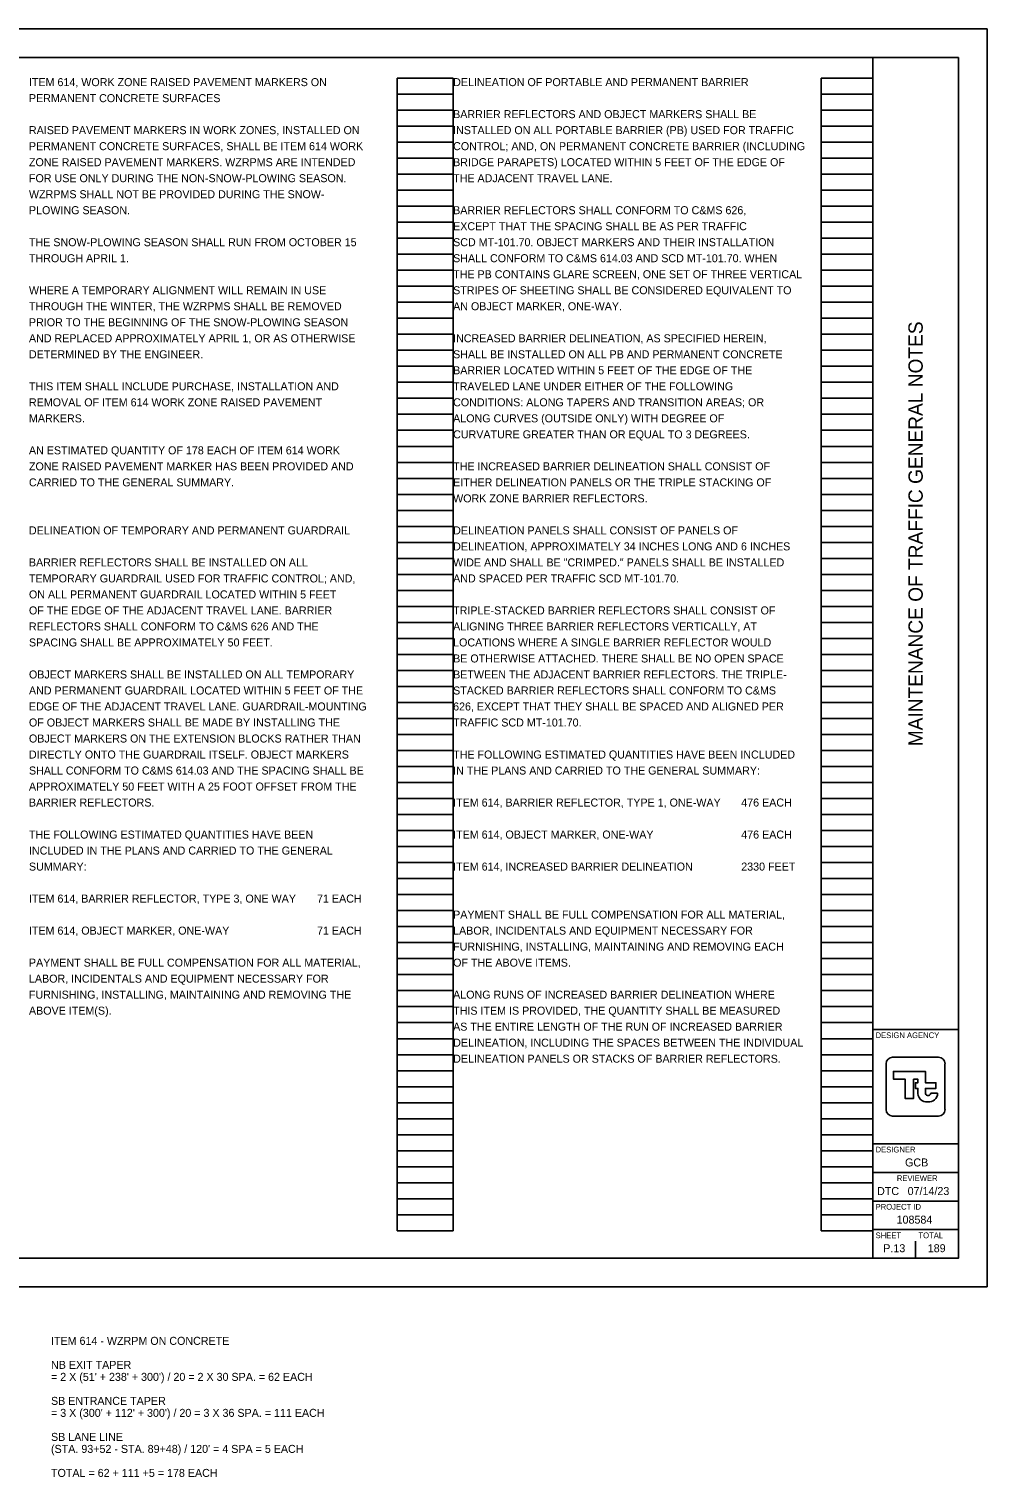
# Model space of a CAD drawing. Extents: x 0 to 34, y -4 to 22.
# Drawn here: x 17.24 to 34, y -3.33 to 22 of the extents above; entities that cross this region are included whole.
import ezdxf

# ---------------------------------------------------------------- set-up
doc = ezdxf.new("R2010")
doc.units = 0
for name, color, linetype in [('SH_Border', 7, 'Continuous'), ('SH_Cut_Line', 7, 'Continuous'), ('SH_Data', 7, 'Continuous'), ('SH_Text', 7, 'Continuous')]:
    doc.layers.add(name, color=color, linetype=linetype)

msp = doc.modelspace()

# ---------------------------------------------------------------- linework, layer by layer
at = {"layer": 'SH_Border'}
for p, q in [((32, 0.5), (32, 21.5)), ((32, 4.5), (33.5, 4.5)), ((32, 2.5), (33.5, 2.5)), ((32, 2), (33.5, 2)), ((32, 1.5), (33.5, 1.5)), ((32, 1), (33.5, 1))]:
    msp.add_line(p, q, dxfattribs=at)
msp.add_lwpolyline([(1.5, 21.5), (33.5, 21.5), (33.5, 0.5), (1.5, 0.5)], close=True, dxfattribs=at)
at = {"layer": 'SH_Cut_Line'}
msp.add_lwpolyline([(0, 0), (34, 0), (34, 22), (0, 22)], close=True, dxfattribs=at)
at = {"layer": 'SH_Data'}
for p, q in [((23.68, 0.98), (23.68, 21.14)), ((23.68, 21.14), (24.66, 21.14)), ((24.66, 0.98), (24.66, 21.14)), ((31.1, 0.98), (31.1, 21.14)), ((31.1, 21.14), (32, 21.14)), ((32, 0.98), (32, 21.14)), ((23.68, 20.86), (24.66, 20.86)), ((31.1, 20.86), (32, 20.86)), ((23.68, 20.58), (24.66, 20.58)), ((31.1, 20.58), (32, 20.58)), ((23.68, 20.3), (24.66, 20.3)), ((31.1, 20.3), (32, 20.3)), ((23.68, 20.02), (24.66, 20.02)), ((31.1, 20.02), (32, 20.02)), ((23.68, 19.74), (24.66, 19.74)), ((31.1, 19.74), (32, 19.74)), ((23.68, 19.46), (24.66, 19.46)), ((31.1, 19.46), (32, 19.46)), ((23.68, 19.18), (24.66, 19.18)), ((31.1, 19.18), (32, 19.18)), ((23.68, 18.9), (24.66, 18.9)), ((31.1, 18.9), (32, 18.9)), ((23.68, 18.62), (24.66, 18.62)), ((31.1, 18.62), (32, 18.62)), ((23.68, 18.34), (24.66, 18.34)), ((31.1, 18.34), (32, 18.34)), ((23.68, 18.06), (24.66, 18.06)), ((31.1, 18.06), (32, 18.06)), ((23.68, 17.78), (24.66, 17.78)), ((31.1, 17.78), (32, 17.78)), ((23.68, 17.5), (24.66, 17.5)), ((31.1, 17.5), (32, 17.5)), ((23.68, 17.22), (24.66, 17.22)), ((31.1, 17.22), (32, 17.22)), ((23.68, 16.94), (24.66, 16.94)), ((31.1, 16.94), (32, 16.94)), ((23.68, 16.66), (24.66, 16.66)), ((31.1, 16.66), (32, 16.66)), ((23.68, 16.38), (24.66, 16.38)), ((31.1, 16.38), (32, 16.38)), ((23.68, 16.1), (24.66, 16.1)), ((31.1, 16.1), (32, 16.1)), ((23.68, 15.82), (24.66, 15.82)), ((31.1, 15.82), (32, 15.82)), ((23.68, 15.54), (24.66, 15.54)), ((31.1, 15.54), (32, 15.54)), ((23.68, 15.26), (24.66, 15.26)), ((31.1, 15.26), (32, 15.26)), ((23.68, 14.98), (24.66, 14.98)), ((31.1, 14.98), (32, 14.98)), ((23.68, 14.7), (24.66, 14.7)), ((31.1, 14.7), (32, 14.7)), ((23.68, 14.42), (24.66, 14.42)), ((31.1, 14.42), (32, 14.42)), ((23.68, 14.14), (24.66, 14.14)), ((31.1, 14.14), (32, 14.14)), ((23.68, 13.86), (24.66, 13.86)), ((31.1, 13.86), (32, 13.86)), ((23.68, 13.58), (24.66, 13.58)), ((31.1, 13.58), (32, 13.58)), ((23.68, 13.3), (24.66, 13.3)), ((31.1, 13.3), (32, 13.3)), ((23.68, 13.02), (24.66, 13.02)), ((31.1, 13.02), (32, 13.02)), ((23.68, 12.74), (24.66, 12.74)), ((31.1, 12.74), (32, 12.74)), ((23.68, 12.46), (24.66, 12.46)), ((31.1, 12.46), (32, 12.46)), ((23.68, 12.18), (24.66, 12.18)), ((31.1, 12.18), (32, 12.18)), ((23.68, 11.9), (24.66, 11.9)), ((31.1, 11.9), (32, 11.9)), ((23.68, 11.62), (24.66, 11.62)), ((31.1, 11.62), (32, 11.62)), ((23.68, 11.34), (24.66, 11.34)), ((31.1, 11.34), (32, 11.34)), ((23.68, 11.06), (24.66, 11.06)), ((31.1, 11.06), (32, 11.06)), ((23.68, 10.78), (24.66, 10.78)), ((31.1, 10.78), (32, 10.78)), ((23.68, 10.5), (24.66, 10.5)), ((31.1, 10.5), (32, 10.5)), ((23.68, 10.22), (24.66, 10.22)), ((31.1, 10.22), (32, 10.22)), ((23.68, 9.94), (24.66, 9.94)), ((31.1, 9.94), (32, 9.94)), ((23.68, 9.66), (24.66, 9.66)), ((31.1, 9.66), (32, 9.66)), ((23.68, 9.38), (24.66, 9.38)), ((31.1, 9.38), (32, 9.38)), ((23.68, 9.1), (24.66, 9.1)), ((31.1, 9.1), (32, 9.1)), ((23.68, 8.82), (24.66, 8.82)), ((31.1, 8.82), (32, 8.82)), ((23.68, 8.54), (24.66, 8.54)), ((31.1, 8.54), (32, 8.54)), ((23.68, 8.26), (24.66, 8.26)), ((31.1, 8.26), (32, 8.26)), ((23.68, 7.98), (24.66, 7.98)), ((31.1, 7.98), (32, 7.98)), ((23.68, 7.7), (24.66, 7.7)), ((31.1, 7.7), (32, 7.7)), ((23.68, 7.42), (24.66, 7.42)), ((31.1, 7.42), (32, 7.42)), ((23.68, 7.14), (24.66, 7.14)), ((31.1, 7.14), (32, 7.14)), ((23.68, 6.86), (24.66, 6.86)), ((31.1, 6.86), (32, 6.86)), ((23.68, 6.58), (24.66, 6.58)), ((31.1, 6.58), (32, 6.58)), ((23.68, 6.3), (24.66, 6.3)), ((31.1, 6.3), (32, 6.3)), ((23.68, 6.02), (24.66, 6.02)), ((31.1, 6.02), (32, 6.02)), ((23.68, 5.74), (24.66, 5.74)), ((31.1, 5.74), (32, 5.74)), ((23.68, 5.46), (24.66, 5.46)), ((31.1, 5.46), (32, 5.46)), ((23.68, 5.18), (24.66, 5.18)), ((31.1, 5.18), (32, 5.18)), ((23.68, 4.9), (24.66, 4.9)), ((31.1, 4.9), (32, 4.9)), ((23.68, 4.62), (24.66, 4.62)), ((31.1, 4.62), (32, 4.62)), ((23.68, 4.34), (24.66, 4.34)), ((31.1, 4.34), (32, 4.34)), ((23.68, 4.06), (24.66, 4.06)), ((31.1, 4.06), (32, 4.06)), ((23.68, 3.78), (24.66, 3.78)), ((31.1, 3.78), (32, 3.78)), ((23.68, 3.5), (24.66, 3.5)), ((31.1, 3.5), (32, 3.5)), ((32.75, 3.5), (32.75, 3.5)), ((32.791, 3.415), (32.791, 3.415)), ((33.136, 3.385), (33.015, 3.385)), ((23.68, 3.22), (24.66, 3.22)), ((31.1, 3.22), (32, 3.22)), ((23.68, 2.94), (24.66, 2.94)), ((31.1, 2.94), (32, 2.94)), ((23.68, 2.66), (24.66, 2.66)), ((31.1, 2.66), (32, 2.66)), ((23.68, 2.38), (24.66, 2.38)), ((31.1, 2.38), (32, 2.38)), ((23.68, 2.1), (24.66, 2.1)), ((31.1, 2.1), (32, 2.1)), ((23.68, 1.82), (24.66, 1.82)), ((31.1, 1.82), (32, 1.82)), ((23.68, 1.54), (24.66, 1.54)), ((31.1, 1.54), (32, 1.54)), ((23.68, 1.26), (24.66, 1.26)), ((31.1, 1.26), (32, 1.26)), ((23.68, 0.98), (24.66, 0.98)), ((31.1, 0.98), (32, 0.98)), ((32.75, 0.5), (32.75, 0.8)), ((32.375, 0.675), (32.375, 0.675))]:
    msp.add_line(p, q, dxfattribs=at)
for points in [[(32.236, 3.099), (32.236, 3.901)], [(32.348, 4.014), (33.152, 4.014)], [(33.264, 3.901), (33.264, 3.099)], [(32.922, 3.399), (32.922, 3.47), (33.107, 3.47), (33.107, 3.568), (32.922, 3.568), (32.922, 3.768), (32.361, 3.768), (32.361, 3.632), (32.566, 3.632), (32.566, 3.294), (32.715, 3.294), (32.715, 3.63), (32.79, 3.63), (32.79, 3.568), (32.748, 3.568), (32.748, 3.47), (32.79, 3.47), (32.79, 3.415), (32.791, 3.415)], [(33.152, 2.986), (32.348, 2.986)]]:
    msp.add_lwpolyline(points, dxfattribs=at)
for centre, radius, start, end in [((32.348, 3.901), 0.113, 90, 180), ((33.152, 3.901), 0.113, 360, 90), ((32.949, 3.392), 0.16, 171.8856, 274.8323), ((32.968, 3.392), 0.0473, 171.8856, 350.9243), ((32.976, 3.392), 0.16, 265.1677, 357.3201), ((32.348, 3.099), 0.113, 180, 270), ((33.152, 3.099), 0.113, 270, 360)]:
    msp.add_arc(centre, radius, start, end, dxfattribs=at)

# ---------------------------------------------------------------- texts
msp.add_text('MAINTENANCE OF TRAFFIC GENERAL NOTES', height=0.25, rotation=90, dxfattribs=at).set_placement((32.875, 9.455))
for s, height, p in [('DESIGN AGENCY', 0.1, (32.05, 4.35)), ('DESIGNER', 0.1, (32.05, 2.35)), ('GCB', 0.14, (32.566, 2.105)), ('REVIEWER', 0.1, (32.422, 1.85)), ('DTC', 0.14, (32.076, 1.605)), ('07/14/23', 0.14, (32.611, 1.605)), ('PROJECT ID', 0.1, (32.05, 1.35)), ('108584', 0.14, (32.418, 1.105)), ('SHEET', 0.1, (32.05, 0.85)), ('TOTAL', 0.1, (32.8, 0.85)), ('P.13', 0.14, (32.185, 0.605)), ('189', 0.14, (32.963, 0.605))]:
    msp.add_text(s, height=height, dxfattribs=at).set_placement(p)
at = {"layer": 'SH_Text'}
for s, p in [('ITEM 614, WORK ZONE RAISED PAVEMENT MARKERS ON', (17.24, 21)), ('DELINEATION OF PORTABLE AND PERMANENT BARRIER', (24.66, 21)), ('PERMANENT CONCRETE SURFACES', (17.24, 20.72)), ('BARRIER REFLECTORS AND OBJECT MARKERS SHALL BE', (24.66, 20.44)), ('RAISED PAVEMENT MARKERS IN WORK ZONES, INSTALLED ON', (17.24, 20.16)), ('INSTALLED ON ALL PORTABLE BARRIER (PB) USED FOR TRAFFIC', (24.66, 20.16)), ('PERMANENT CONCRETE SURFACES, SHALL BE ITEM 614 WORK', (17.24, 19.88)), ('CONTROL; AND, ON PERMANENT CONCRETE BARRIER (INCLUDING', (24.66, 19.88)), ('ZONE RAISED PAVEMENT MARKERS. WZRPMS ARE INTENDED', (17.24, 19.6)), ('BRIDGE PARAPETS) LOCATED WITHIN 5 FEET OF THE EDGE OF', (24.66, 19.6)), ('FOR USE ONLY DURING THE NON-SNOW-PLOWING SEASON.', (17.24, 19.32)), ('THE ADJACENT TRAVEL LANE.', (24.66, 19.32)), ('WZRPMS SHALL NOT BE PROVIDED DURING THE SNOW-', (17.24, 19.04)), ('PLOWING SEASON.', (17.24, 18.76)), ('BARRIER REFLECTORS SHALL CONFORM TO C&MS 626,', (24.66, 18.76)), ('EXCEPT THAT THE SPACING SHALL BE AS PER TRAFFIC', (24.66, 18.48)), ('THE SNOW-PLOWING SEASON SHALL RUN FROM OCTOBER 15', (17.24, 18.2)), ('SCD MT-101.70. OBJECT MARKERS AND THEIR INSTALLATION', (24.66, 18.2)), ('THROUGH APRIL 1.', (17.24, 17.92)), ('SHALL CONFORM TO C&MS 614.03 AND SCD MT-101.70. WHEN', (24.66, 17.92)), ('THE PB CONTAINS GLARE SCREEN, ONE SET OF THREE VERTICAL', (24.66, 17.64)), ('WHERE A TEMPORARY ALIGNMENT WILL REMAIN IN USE', (17.24, 17.36)), ('STRIPES OF SHEETING SHALL BE CONSIDERED EQUIVALENT TO', (24.66, 17.36)), ('THROUGH THE WINTER, THE WZRPMS SHALL BE REMOVED', (17.24, 17.08)), ('AN OBJECT MARKER, ONE-WAY.', (24.66, 17.08)), ('PRIOR TO THE BEGINNING OF THE SNOW-PLOWING SEASON', (17.24, 16.8)), ('AND REPLACED APPROXIMATELY APRIL 1, OR AS OTHERWISE', (17.24, 16.52)), ('INCREASED BARRIER DELINEATION, AS SPECIFIED HEREIN,', (24.66, 16.52)), ('DETERMINED BY THE ENGINEER.', (17.24, 16.24)), ('SHALL BE INSTALLED ON ALL PB AND PERMANENT CONCRETE', (24.66, 16.24)), ('BARRIER LOCATED WITHIN 5 FEET OF THE EDGE OF THE', (24.66, 15.96)), ('THIS ITEM SHALL INCLUDE PURCHASE, INSTALLATION AND', (17.24, 15.68)), ('TRAVELED LANE UNDER EITHER OF THE FOLLOWING', (24.66, 15.68)), ('REMOVAL OF ITEM 614 WORK ZONE RAISED PAVEMENT', (17.24, 15.4)), ('CONDITIONS: ALONG TAPERS AND TRANSITION AREAS; OR', (24.66, 15.4)), ('MARKERS.', (17.24, 15.12)), ('ALONG CURVES (OUTSIDE ONLY) WITH DEGREE OF', (24.66, 15.12)), ('CURVATURE GREATER THAN OR EQUAL TO 3 DEGREES.', (24.66, 14.84)), ('AN ESTIMATED QUANTITY OF 178 EACH OF ITEM 614 WORK', (17.24, 14.56)), ('ZONE RAISED PAVEMENT MARKER HAS BEEN PROVIDED AND', (17.24, 14.28)), ('THE INCREASED BARRIER DELINEATION SHALL CONSIST OF', (24.66, 14.28)), ('CARRIED TO THE GENERAL SUMMARY.', (17.24, 14)), ('EITHER DELINEATION PANELS OR THE TRIPLE STACKING OF', (24.66, 14)), ('WORK ZONE BARRIER REFLECTORS.', (24.66, 13.72)), ('DELINEATION OF TEMPORARY AND PERMANENT GUARDRAIL', (17.24, 13.16)), ('DELINEATION PANELS SHALL CONSIST OF PANELS OF', (24.66, 13.16)), ('DELINEATION, APPROXIMATELY 34 INCHES LONG AND 6 INCHES', (24.66, 12.88)), ('BARRIER REFLECTORS SHALL BE INSTALLED ON ALL', (17.24, 12.6)), ('WIDE AND SHALL BE "CRIMPED." PANELS SHALL BE INSTALLED', (24.66, 12.6)), ('TEMPORARY GUARDRAIL USED FOR TRAFFIC CONTROL; AND,', (17.24, 12.32)), ('AND SPACED PER TRAFFIC SCD MT-101.70.', (24.66, 12.32)), ('ON ALL PERMANENT GUARDRAIL LOCATED WITHIN 5 FEET', (17.24, 12.04)), ('OF THE EDGE OF THE ADJACENT TRAVEL LANE. BARRIER', (17.24, 11.76)), ('TRIPLE-STACKED BARRIER REFLECTORS SHALL CONSIST OF', (24.66, 11.76)), ('REFLECTORS SHALL CONFORM TO C&MS 626 AND THE', (17.24, 11.48)), ('ALIGNING THREE BARRIER REFLECTORS VERTICALLY, AT', (24.66, 11.48)), ('SPACING SHALL BE APPROXIMATELY 50 FEET.', (17.24, 11.2)), ('LOCATIONS WHERE A SINGLE BARRIER REFLECTOR WOULD', (24.66, 11.2)), ('BE OTHERWISE ATTACHED. THERE SHALL BE NO OPEN SPACE', (24.66, 10.92)), ('OBJECT MARKERS SHALL BE INSTALLED ON ALL TEMPORARY', (17.24, 10.64)), ('BETWEEN THE ADJACENT BARRIER REFLECTORS. THE TRIPLE-', (24.66, 10.64)), ('AND PERMANENT GUARDRAIL LOCATED WITHIN 5 FEET OF THE', (17.24, 10.36)), ('STACKED BARRIER REFLECTORS SHALL CONFORM TO C&MS', (24.66, 10.36)), ('EDGE OF THE ADJACENT TRAVEL LANE. GUARDRAIL-MOUNTING', (17.24, 10.08)), ('626, EXCEPT THAT THEY SHALL BE SPACED AND ALIGNED PER', (24.66, 10.08)), ('OF OBJECT MARKERS SHALL BE MADE BY INSTALLING THE', (17.24, 9.8)), ('TRAFFIC SCD MT-101.70.', (24.66, 9.8)), ('OBJECT MARKERS ON THE EXTENSION BLOCKS RATHER THAN', (17.24, 9.52)), ('DIRECTLY ONTO THE GUARDRAIL ITSELF. OBJECT MARKERS', (17.24, 9.24)), ('THE FOLLOWING ESTIMATED QUANTITIES HAVE BEEN INCLUDED', (24.66, 9.24)), ('SHALL CONFORM TO C&MS 614.03 AND THE SPACING SHALL BE', (17.24, 8.96)), ('IN THE PLANS AND CARRIED TO THE GENERAL SUMMARY:', (24.66, 8.96)), ('APPROXIMATELY 50 FEET WITH A 25 FOOT OFFSET FROM THE', (17.24, 8.68)), ('BARRIER REFLECTORS.', (17.24, 8.4)), ('ITEM 614, BARRIER REFLECTOR, TYPE 1, ONE-WAY', (24.66, 8.4)), ('476 EACH', (29.7, 8.4)), ('THE FOLLOWING ESTIMATED QUANTITIES HAVE BEEN', (17.24, 7.84)), ('ITEM 614, OBJECT MARKER, ONE-WAY', (24.66, 7.84)), ('476 EACH', (29.7, 7.84)), ('INCLUDED IN THE PLANS AND CARRIED TO THE GENERAL', (17.24, 7.56)), ('SUMMARY:', (17.24, 7.28)), ('ITEM 614, INCREASED BARRIER DELINEATION', (24.66, 7.28)), ('2330 FEET', (29.7, 7.28)), ('ITEM 614, BARRIER REFLECTOR, TYPE 3, ONE WAY', (17.24, 6.72)), ('71 EACH', (22.28, 6.72)), ('PAYMENT SHALL BE FULL COMPENSATION FOR ALL MATERIAL,', (24.66, 6.44)), ('ITEM 614, OBJECT MARKER, ONE-WAY', (17.24, 6.16)), ('71 EACH', (22.28, 6.16)), ('LABOR, INCIDENTALS AND EQUIPMENT NECESSARY FOR', (24.66, 6.16)), ('FURNISHING, INSTALLING, MAINTAINING AND REMOVING EACH', (24.66, 5.88)), ('PAYMENT SHALL BE FULL COMPENSATION FOR ALL MATERIAL,', (17.24, 5.6)), ('OF THE ABOVE ITEMS.', (24.66, 5.6)), ('LABOR, INCIDENTALS AND EQUIPMENT NECESSARY FOR', (17.24, 5.32)), ('FURNISHING, INSTALLING, MAINTAINING AND REMOVING THE', (17.24, 5.04)), ('ALONG RUNS OF INCREASED BARRIER DELINEATION WHERE', (24.66, 5.04)), ('ABOVE ITEM(S).', (17.24, 4.76)), ('THIS ITEM IS PROVIDED, THE QUANTITY SHALL BE MEASURED', (24.66, 4.76)), ('AS THE ENTIRE LENGTH OF THE RUN OF INCREASED BARRIER', (24.66, 4.48)), ('DELINEATION, INCLUDING THE SPACES BETWEEN THE INDIVIDUAL', (24.66, 4.2)), ('DELINEATION PANELS OR STACKS OF BARRIER REFLECTORS.', (24.66, 3.92)), ('ITEM 614 - WZRPM ON CONCRETE', (17.626, -1.015)), ("= 2 X (51' + 238' + 300') / 20 = 2 X 30 SPA. = 62 EACH", (17.626, -1.645)), ('NB EXIT TAPER ', (17.626, -1.435)), ('SB ENTRANCE TAPER', (17.626, -2.065)), ("= 3 X (300' + 112' + 300') / 20 = 3 X 36 SPA. = 111 EACH", (17.626, -2.275)), ('SB LANE LINE', (17.626, -2.695)), ("(STA. 93+52 - STA. 89+48) / 120' = 4 SPA = 5 EACH", (17.626, -2.905)), ('TOTAL = 62 + 111 +5 = 178 EACH', (17.626, -3.325))]:
    msp.add_text(s, height=0.14, dxfattribs=at).set_placement(p)

doc.saveas('drawing.dxf')
